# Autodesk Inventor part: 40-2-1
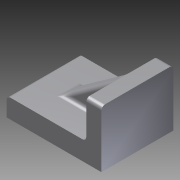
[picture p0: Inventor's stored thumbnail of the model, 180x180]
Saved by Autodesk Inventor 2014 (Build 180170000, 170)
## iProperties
Created: 2014-01
Part Number: 40-2-1
Document SubType Name: Modeling
Designer: Administrator
Density: 1 g/cm^3
Material: 常规
Appearance: 默认
Author: Administrator
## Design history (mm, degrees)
sketch "草图1"
  geometry: L1 (-12.5, 9.5)-(12.5, 9.5); L2 (12.5, 9.5)-(12.5, -9.5); L3 (12.5, -9.5)-(-12.5, -9.5); L4 (-12.5, -9.5)-(-12.5, 9.5); 3 further points
  constraints: 8 end point, 2 midpoint, 2 parallel, 1 horizontal, 1 horizontal alignment, 1 perpendicular, 1 vertical alignment
  dimensions: "d0" = 25 distance of L1.start L1.end; "d1" = 19 distance of L1.end L2.end
extrude "拉伸1" new body sketch "草图1" distance "d2" = 5; taper "d3" = 0 deg
sketch "草图2"
  geometry: L1 (12.5, -9.5)-(-12.5, -9.5) reference; L2 (12.5, 9.5)-(8.5, 9.5); L3 (8.5, 9.5)-(8.5, -9.5); L4 (8.5, -9.5)-(12.5, -9.5); L5 (12.5, -9.5)-(12.5, 9.5); 1 further point
  constraints: 8 end point, 2 parallel, 1 horizontal, 1 perpendicular, 1 point on line
  dimensions: "d4" = 4 distance between parallel lines of L5 L3
extrude "拉伸2" join sketch "草图2" distance "d5" = 10; taper "d6" = 0 deg
sketch "草图3"
  geometry: L1 (-8.5, 5)-(-8.5, 15) reference; L2 (-8.5, 15)-(-12.5, 15) reference; L3 (12.5, 5)-(-8.5, 5) reference; L4 (-8.5, 15)-(5.5, 5); 1 further point
  constraints: 2 end point, 1 point on line
  dimensions: "d7" = 7 distance of L4.end L3.start
feature "加强筋1" sketch "草图3" dims "d8" = 1, "d9" = 4, "d10" = 0
fillet "圆角1" dims "d11" = 1
fillet "圆角2" dims "d12" = 1
fillet "圆角3" dims "d13" = 1
node "实体1"
